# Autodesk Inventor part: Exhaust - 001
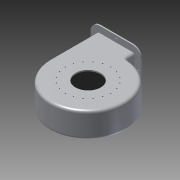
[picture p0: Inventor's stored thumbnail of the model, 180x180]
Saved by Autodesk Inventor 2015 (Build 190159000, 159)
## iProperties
Created: 2006-05
Part Number: Exhaust - 001
Document SubType Name: Modeling
Designer: Autodesk, Inc.
Density: 2.71 g/cm^3
Material: Aluminum-6061
Mass: 27045.4 g
Surface Area: 19920.1 cm^2
Volume: 9979.84 cm^3
Appearance: Aluminum - Flat
Author: Autodesk, Inc.
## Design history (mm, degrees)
derived "MainGeom.ipt"
sketch "Sketch1" dims "d42" = 600
  geometry: L1 (0, 370)-(-300, 370); L2 (-300, 0)-(-300, 370); L3 (-200, 0)-(-200, -350); L4 (-200, -350)-(200, -350); L5 (200, -350)-(200, 0); L6 (0, 370)-(0, 300); C1 r 100 at (0, 0); C2 r 25 at (0, 0); A1 r 200 centre (0, 0) between (200, 0) and (-200, 0); 2 further points
  constraints: 12 end point, 3 centre point, 3 vertical, 2 horizontal, 2 point on circle, 2 point on line, 1 coincident, 5 other
  dimensions: "d41" = 50 diameter of C2; "d43" = 200 radius of A1; "d44" = 200 diameter of C1; "d45" = 350 distance from line of L4 point (0, 0); "d46" = 370 distance from line of L1 point (0, 0)
extrude "Extrusion1" new body sketch "Sketch1" distance "d1" = 200; taper "d2" = 0 deg
fillet "Fillet1" dims "d37" = 20
sketch "Sketch12"
  geometry: L1 (-20, -20)-(-20, -180) reference; L2 (0, -200)-(260, -200) reference; L3 (280, -20)-(280, -180) reference; L4 (260, 0)-(0, 0) reference; L5 (-70, -20)-(-70, -180); L6 (0, -250)-(260, -250); L7 (330, -180)-(330, -20); L8 (260, 50)-(0, 50); L9 (-50, -20)-(-50, -180); L10 (0, -230)-(260, -230); L11 (310, -180)-(310, -20); L12 (260, 30)-(0, 30); C1 r 6.35 at (130, 30); C2 r 6.35 at (-50, -100); C3 r 6.35 at (130, -230); C4 r 6.35 at (310, -100); A1 r 20 centre (0, -20) between (0, 0) and (-20, -20) reference; A2 r 20 centre (0, -180) between (-20, -180) and (0, -200) reference; A3 r 20 centre (260, -180) between (260, -200) and (280, -180) reference; A4 r 20 centre (260, -20) between (280, -20) and (260, 0) reference; A5 r 70 centre (0, -20) between (0, 50) and (-70, -20); A6 r 70 centre (0, -180) between (-70, -180) and (0, -250); A7 r 70 centre (260, -180) between (260, -250) and (330, -180); A8 r 70 centre (260, -20) between (330, -20) and (260, 50); A9 r 50 centre (0, -20) between (0, 30) and (-50, -20); A10 r 50 centre (0, -180) between (-50, -180) and (0, -230); A11 r 50 centre (260, -180) between (260, -230) and (310, -180); A12 r 50 centre (260, -20) between (310, -20) and (260, 30); 5 further points
  constraints: 16 end point, 16 point on circle, 12 centre point, 4 coincident, 4 midpoint, 3 equal radius, 14 other
  dimensions: "d54" = 50 distance between parallel lines of L8 L4; "d55" = 30 distance between parallel lines of L4 L12; "d58" = 400 distance between parallel lines of L7 L5 (derived); "d59" = 300 distance between parallel lines of L6 L8 (derived); "d60" = 12.7 diameter of C3
  node "Projected Loop2"
extrude "Extrusion8" join sketch "Sketch12" distance "d47" = 10.16 (= Thickness); taper "d48" = 0 deg
shell "Shell1" dims "d17" = 10.16 (= Thickness)
extrude "Extrusion4" cut sketch "Sketch1" stored distance "d18" = 100; taper "d19" = 0 deg
extrude "Extrusion9" cut sketch "Sketch1" stored distance "d49" = 10.16 (= Thickness); taper "d50" = 0 deg
sketch "Sketch8" dims "d26" = 360
  geometry: 3 further points
  constraints: 2 vertical alignment, 1 coincident, 2 other
hole "Hole1" sketch "Sketch8" at (280, -190) diameter "d27" = 7.7978; stored, may be unused: countersink angle "d31" = 90 deg, drill point angle "d33" = 118 deg; dims "d28" = 6, "d29" = 4, "d30" = 2, "d32" = 8
extrude "Extrusion10" cut sketch "Sketch12" stored distance "d56" = 10.16 (= Thickness); taper "d57" = 0 deg
body "Solid1"
pattern_circular "Circular Pattern2" dims angle "d52" = 360 deg
other parameters: "Thickness" = 10.16 [user parameter; used in 4 equation terms]
